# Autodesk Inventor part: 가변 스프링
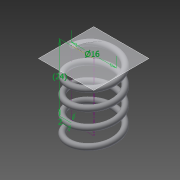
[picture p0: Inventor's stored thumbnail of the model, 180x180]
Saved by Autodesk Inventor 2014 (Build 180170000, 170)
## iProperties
Created: 2015-04
Part Number: 가변 스프링
Material: Generic
Document SubType Name: Modeling
Designer: Administrator
Density: 1 g/cm^3
Appearance: Default
Mass: 0.606913 g
Surface Area: 12.5215 cm^2
Volume: 0.606913 cm^3
Author: Administrator
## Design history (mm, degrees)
sketch "스케치1"
  geometry: L1 (0, 0)-(-8, 0); L2 (-8, 0)-(-8, 11.5); L3 (-8, 11.5)-(0, 11.5); L4 (0, 11.5)-(0, 0); C1 r 1 at (-8, 0)
  constraints: 8 end point, 2 parallel, 1 centre point, 1 coincident, 1 horizontal, 1 perpendicular
  dimensions: "d0" = 16 diameter of L2 L4; "d1" = 11.50049 distance between parallel lines of L1 L3 (derived); "d2" = 2 diameter of C1
feature "코일1" pitch "d3" = 10; turns "d5" = 4; dims "d4" = 11.50049 (= d1), "d6" = 0, angle "d7" = 90 deg, angle "d8" = 90 deg, "d9" = 0, "d10" = 0
sketch "스케치2"
  geometry: L1 (9, 0)-(7, 0) reference; 1 further point
  constraints: 1 horizontal alignment
extrude "돌출1" cut sketch "스케치2" stored distance "d11" = 10; taper "d12" = 0 deg
node "작업 평면1"
sketch "스케치3"
  geometry: L1 (7, 0)-(9, 0) reference; 1 further point
  constraints: 1 horizontal alignment
extrude "돌출2" cut sketch "스케치3" stored distance "d13" = 10; taper "d14" = 0 deg
node "솔리드1"
node "절단 모서리 투영1"
node "절단 모서리 투영2"
